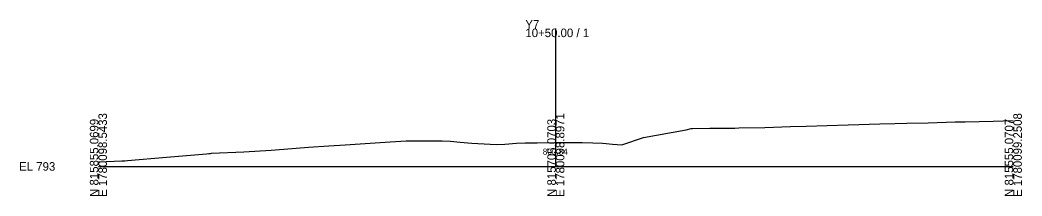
# Model space of a CAD drawing. Extents: x -26 to 2903, y -10 to 5536.
# Drawn here: x -25.7 to 302.8, y 490.3 to 548 of the extents above; entities that cross this region are included whole.
import ezdxf

# ---------------------------------------------------------------- set-up
doc = ezdxf.new("R2010")
doc.units = 0
for name, color, linetype in [('Exist Cross Section Cell', 7, 'Continuous'), ('Exist XS Center Line Elevation Label', 7, 'Continuous'), ('Exist XS Ground Line', 7, 'Continuous')]:
    doc.layers.add(name, color=color, linetype=linetype)

msp = doc.modelspace()

# ---------------------------------------------------------------- linework, layer by layer
at = {"layer": 'Exist Cross Section Cell'}
for p, q in [((150, 500), (150, 545.22)), ((0, 500), (150, 500)), ((150, 500), (300, 500))]:
    msp.add_line(p, q, dxfattribs=at)
at = {"layer": 'Exist XS Ground Line'}
for p, q in [((200.44, 512.5), (208.72, 512.58)), ((208.72, 512.58), (209.98, 512.61)), ((209.98, 512.61), (218.52, 512.81)), ((218.52, 512.81), (226.98, 513.12)), ((226.98, 513.12), (232.11, 513.25)), ((232.11, 513.25), (245.8, 513.6)), ((245.8, 513.6), (256.22, 513.96)), ((256.22, 513.96), (261.11, 514.09)), ((261.11, 514.09), (265.06, 514.19)), ((265.06, 514.19), (272.1, 514.29)), ((272.1, 514.29), (280.9, 514.59)), ((280.9, 514.59), (282.65, 514.61)), ((282.65, 514.61), (284.22, 514.65)), ((284.22, 514.65), (293.43, 514.87)), ((293.43, 514.87), (300, 515.07)), ((171.64, 507.09), (178.77, 509.49)), ((178.77, 509.49), (192.7, 511.98)), ((192.7, 511.98), (194.33, 512.43)), ((194.33, 512.43), (194.81, 512.44)), ((194.81, 512.44), (200.44, 512.5)), ((60.8, 505.7), (68.92, 506.34)), ((68.92, 506.34), (75.58, 506.75)), ((75.58, 506.75), (80.95, 507.07)), ((80.95, 507.07), (95.67, 508.02)), ((95.67, 508.02), (100.94, 508.36)), ((100.94, 508.36), (108.85, 508.39)), ((108.85, 508.39), (112.77, 508.41)), ((112.77, 508.41), (115.48, 508.33)), ((115.48, 508.33), (118.6, 507.93)), ((118.6, 507.93), (122.4, 507.63)), ((122.4, 507.63), (128.48, 507.33)), ((128.48, 507.33), (130.57, 507.17)), ((130.57, 507.17), (133.26, 507.35)), ((133.26, 507.35), (137.09, 507.65)), ((137.09, 507.65), (139.91, 507.74)), ((139.91, 507.74), (143.82, 507.78)), ((143.82, 507.78), (150, 507.84)), ((150, 507.84), (155.25, 507.88)), ((155.25, 507.88), (158.64, 507.88)), ((158.64, 507.88), (162.08, 507.77)), ((162.08, 507.77), (165.29, 507.65)), ((165.29, 507.65), (166.55, 507.56)), ((166.55, 507.56), (168.62, 507.32)), ((168.62, 507.32), (171.64, 507.09)), ((9.49, 501.96), (22.3, 503.07)), ((22.3, 503.07), (35.42, 504.17)), ((35.42, 504.17), (36.19, 504.23)), ((36.19, 504.23), (36.75, 504.29)), ((36.75, 504.29), (37.08, 504.3)), ((37.08, 504.3), (47.65, 504.82)), ((47.65, 504.82), (56.62, 505.37)), ((56.62, 505.37), (60.8, 505.7)), ((0, 501.49), (7.66, 501.82)), ((7.66, 501.82), (8.66, 501.88)), ((8.66, 501.88), (9.49, 501.96))]:
    msp.add_line(p, q, dxfattribs=at)

# ---------------------------------------------------------------- texts
at = {"layer": 'Exist Cross Section Cell'}
for s, p in [('Y7', (140, 545.22)), ('10+50.00 / 1', (140, 542.42)), ('EL 793', (-26, 498.6))]:
    msp.add_text(s, height=2.8, dxfattribs=at).set_placement(p)
for s, p in [('E 1780098.5433', (2.8, 490)), ('E 1780098.8971', (152.8, 490)), ('E 1780099.2508', (302.8, 490)), ('N 815855.0699', (0, 490)), ('N 815705.0703', (150, 490)), ('N 815555.0707', (300, 490))]:
    msp.add_text(s, height=2.8, rotation=90, dxfattribs=at).set_placement(p)
at = {"layer": 'Exist XS Center Line Elevation Label'}
msp.add_text('800.84', height=2, dxfattribs=at).set_placement((145.72, 503.84))

doc.saveas('drawing.dxf')
